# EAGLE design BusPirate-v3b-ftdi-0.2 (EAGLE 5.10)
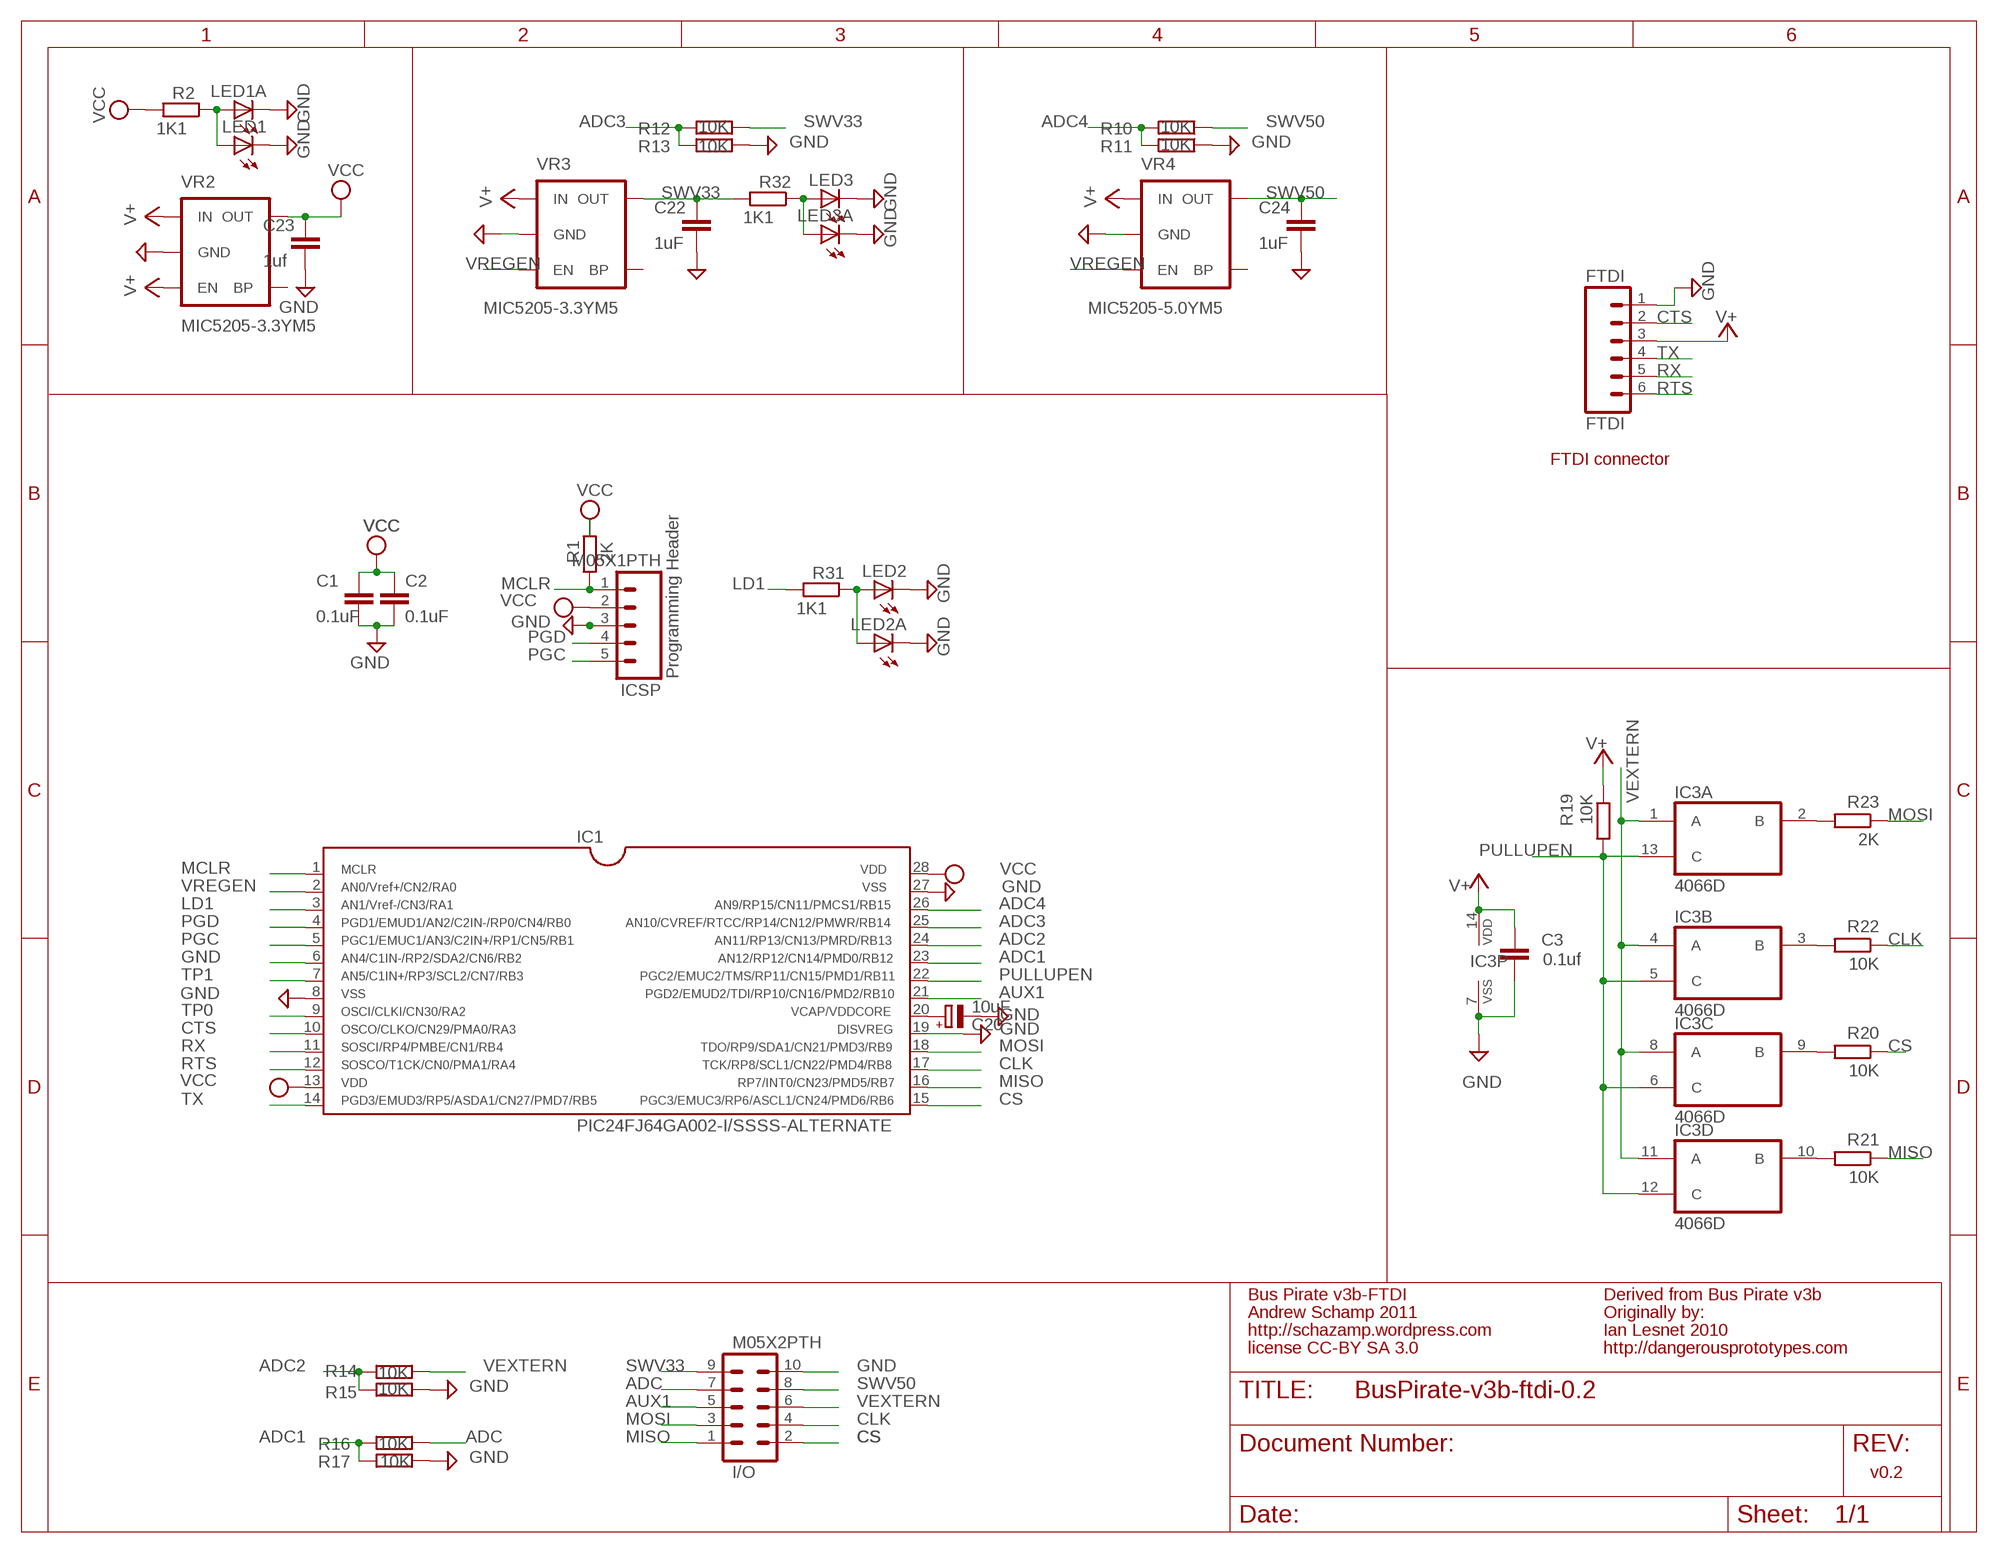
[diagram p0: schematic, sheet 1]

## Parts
C1  0.1uF  C-EUC0805  [C0805]
C2  0.1uF  C-EUC0805  [C0805]
C3  0.1uf  C-EUC0805  [C0805]
C20  10uF  CPOL-EUSMCA  [SMC_A]
C22  1uF  C-EUC0805  [C0805]
C23  1uf  C-EUC0805  [C0805]
C24  1uF  C-EUC0805  [C0805]
FTDI  FTDI  M06LOCK  [1X06_LOCK]
I/O  M05X2PTH  [AVR_ICSP]
IC1  PIC24FJ64GA002-I/SSSS-ALTERNATE  [SSOP28DB]
IC3  4066D  [SO14]
ICSP  M05X1PTH  M05  [1X05]
LED1  LEDCHIP-LED0805  [CHIP-LED0805]
LED1A  LEDCHIP-LED0805  [CHIP-LED0805]
LED2  LEDCHIP-LED0805  [CHIP-LED0805]
LED2A  LEDCHIP-LED0805  [CHIP-LED0805]
LED3  LEDCHIP-LED0805  [CHIP-LED0805]
LED3A  LEDCHIP-LED0805  [CHIP-LED0805]
R1  2K  R-EU_R0805  [R0805]
R2  1K1  R-EU_M0805  [M0805]
R10  10K  R-EU_M0805  [M0805]
R11  10K  R-EU_M0805  [M0805]
R12  10K  R-EU_M0805  [M0805]
R13  10K  R-EU_M0805  [M0805]
R14  10K  R-EU_M0805  [M0805]
R15  10K  R-EU_M0805  [M0805]
R16  10K  R-EU_M0805  [M0805]
R17  10K  R-EU_M0805  [M0805]
R19  10K  R-EU_R0805  [R0805]
R20  10K  R-EU_R0805  [R0805]
R21  10K  R-EU_R0805  [R0805]
R22  10K  R-EU_R0805  [R0805]
R23  2K  R-EU_R0805  [R0805]
R31  1K1  R-EU_M0805  [M0805]
R32  1K1  R-EU_M0805  [M0805]
VR2  MIC5205-3.3YM5  V_REG_LDOSMD  [SOT23-5]
VR3  MIC5205-3.3YM5  V_REG_LDOSMD  [SOT23-5]
VR4  MIC5205-5.0YM5  V_REG_LDOSMD  [SOT23-5]

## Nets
ADC: I/O.7 R16.1
ADC1: IC1.23 R16.2 R17.2
ADC2: IC1.24 R14.2 R15.2
ADC3: IC1.25 R12.2 R13.2
ADC4: IC1.26 R10.2 R11.2
AUX1: I/O.5 IC1.21
CLK: I/O.4 IC1.17 R22.1
CS: I/O.2 IC1.15 R20.1
CTS: FTDI.2 IC1.10
GND: C1.2 C2.2 C3.2 C20.- C22.2 C23.2 C24.2 FTDI.1 I/O.10 IC1.6 IC1.8 IC1.19 IC1.27 IC3.7(P:VSS) ICSP.3 LED1.C LED1A.C LED2.C LED2A.C LED3.C LED3A.C R11.1 R13.1 R15.1 R17.1 VR2.2(GND) VR3.2(GND) VR4.2(GND)
LD1: IC1.3 R31.2
MCLR: IC1.1 ICSP.1 R1.1
MISO: I/O.1 IC1.16 R21.1
MOSI: I/O.3 IC1.18 R23.1
N$1: IC3.2(A:B) R23.2
N$2: IC3.3(B:B) R22.2
N$3: C20.+ IC1.20
N$4: IC3.10(D:B) R21.2
N$5: IC3.9(C:B) R20.2
N$6: LED2.A LED2A.A R31.1
N$7: LED1.A LED1A.A R2.1
N$18: LED3.A LED3A.A R32.1
PGC: IC1.5 ICSP.5
PGD: IC1.4 ICSP.4
PULLUPEN: IC1.22 IC3.5(B:C) IC3.6(C:C) IC3.12(D:C) IC3.13(A:C) R19.2
RTS: FTDI.6 IC1.12
RX: FTDI.5 IC1.11
SWV33: C22.1 I/O.9 R12.1 R32.2 VR3.5(OUT)
SWV50: C24.1 I/O.8 R10.1 VR4.5(OUT)
TP0: IC1.9
TP1: IC1.7
TX: FTDI.4 IC1.14
V+: C3.1 FTDI.3 IC3.14(P:VDD) R19.1 VR2.1(IN) VR2.3(EN) VR3.1(IN) VR4.1(IN)
VCC: C1.1 C2.1 C23.1 IC1.13 IC1.28 ICSP.2 R1.2 R2.2 VR2.5(OUT)
VEXTERN: I/O.6 IC3.1(A:A) IC3.4(B:A) IC3.8(C:A) IC3.11(D:A) R14.1
VREGEN: IC1.2 VR3.3(EN) VR4.3(EN)
Unconnected: VR2.4(BP) VR3.4(BP) VR4.4(BP)

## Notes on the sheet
- FTDI connector
- Programming Header
- Bus Pirate v3b-FTDI | Derived from Bus Pirate v3b
- Andrew Schamp 2011 | Originally by:
- http://schazamp.wordpress.com | Ian Lesnet 2010
- license CC-BY SA 3.0 | http://dangerousprototypes.com
- v0.2

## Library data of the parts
C1-C3 C22-C24 = rcl:C-EU: CAPACITOR, European symbol
C20 = rcl:CPOL-EU: POLARIZED CAPACITOR, European symbol
FTDI = SparkFun:M06: Header 6 Standard 6-pin 0.1" header. Use with straight break away headers (SKU : PRT-00116), right angle break away headers (PRT-00553), swiss pins (PRT-00743), machine pins (PRT-00117), and female headers (PRT-00115). Molex polarized connector foot print use with SKU : PRT-08094 with associated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
I/O = SparkFun:M05X2: Header 5x2 Standard 10-pin dual row 0.1" header. Commonly used with AVR-ISP. Use with Spark Fun Electronics SKU: PRT-00778
IC1 = microchip-pic24:PIC24FJ64GA002-I/SS
IC3 = 40xx:4066: Quad bilateral ANALOG SWITCH
ICSP = SparkFun:M05: Header 5 Standard 5-pin 0.1" header. Use with straight break away headers (SKU : PRT-00116), right angle break away headers (PRT-00553), swiss pins (PRT-00743), machine pins (PRT-00117), and female headers (PRT-00115). Molex polarized connector foot print use with SKU : PRT-08230 with associated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
LED1 LED1A LED2 LED2A LED3 LED3A = led:LED: LED
R1 R2 R19-R23 R31 R32 = rcl:R-EU_: RESISTOR, European symbol
R10-R17 = resistor:R-EU_: RESISTOR, European symbol
VR2-VR4 = SparkFun:V_REG_LDO: Voltage Regulator LDO Standard 150mA LDO voltage regulator in SOT-23 layout. Micrel part MIC5205. BP (by-pass) pin is used to lower output noise with 470pF cap.

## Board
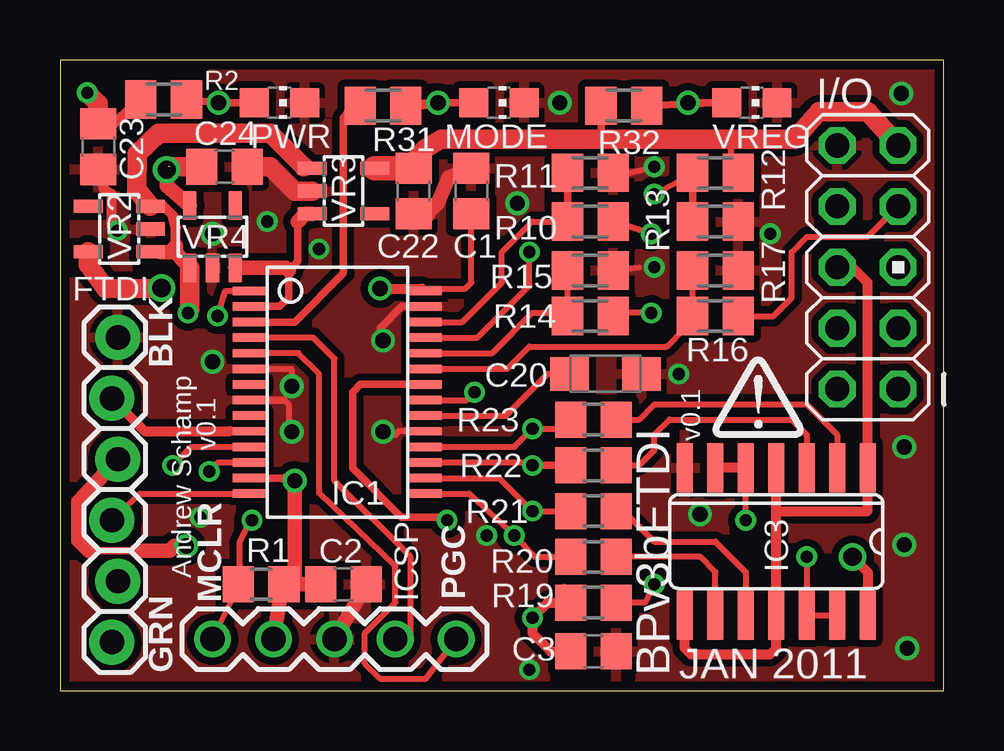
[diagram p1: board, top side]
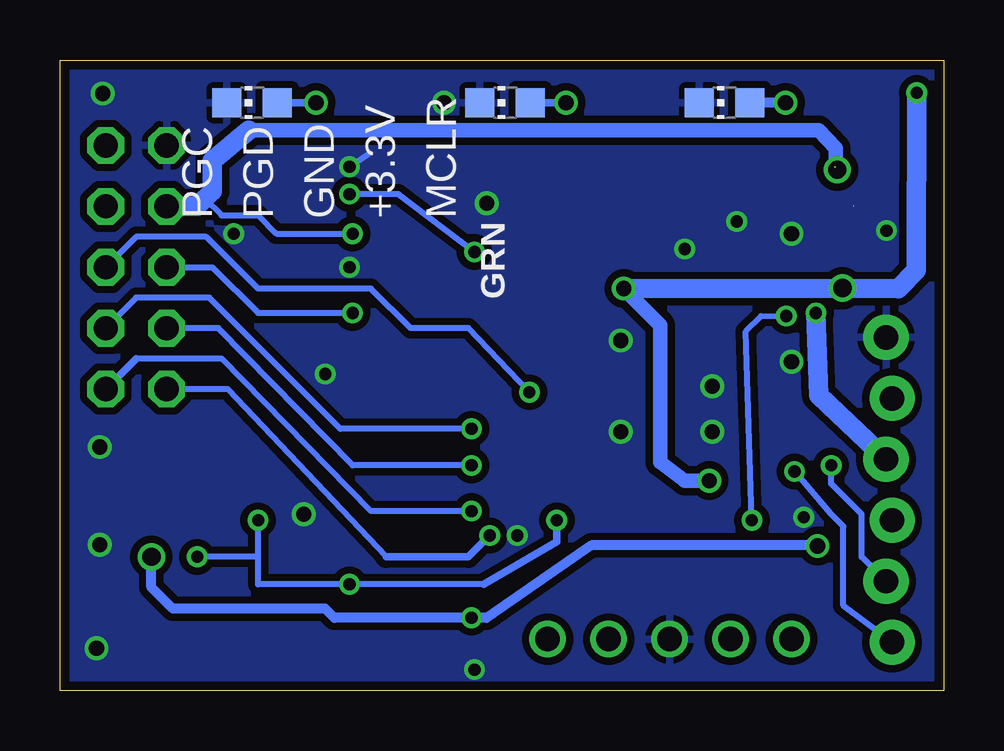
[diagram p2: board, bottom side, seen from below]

Size 36.83 x 26.29 mm. Coordinates in mm from the lower left corner, seen from the top.
Outline: 0,26.29 0,0 36.83,0 36.83,26.29 0,26.29
Copper layers (1*16): Top 0.0356mm / dielectric 1.5011mm / Bottom 0.0356mm
Design rules "LaenPCBOrder-tent": minimum track width 6mil, minimum drill 13mil, track to track 6mil, track to pad 6mil, pad to pad 6mil, via to via 6mil, smd to smd 6mil, copper to edge 15mil, drill to drill 6mil, minimum pad ring 7mil, minimum via ring 7mil, stop-mask expansion 4mil, vias tented up to drill 30mil, thermal gap 10mil

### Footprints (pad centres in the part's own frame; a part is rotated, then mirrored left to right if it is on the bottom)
C0805 = smd 1.3 x 1.5: 1 -0.95,0; 2 0.95,0
SMC_A = smd 1.6 x 1.4: + -1.5,0; - 1.5,0
1X06_LOCK = drill 1.016 pad 1.88 round: 1 0,0; 2 2.54,-0.254; 3 5.08,0; 4 7.62,-0.254; 5 10.16,0; 6 12.7,-0.254
AVR_ICSP = drill 1.016 octagon: 1 -1.27,5.08; 2 1.27,5.08; 3 -1.27,2.54; 4 1.27,2.54; 5 -1.27,0; 6 1.27,0; 7 -1.27,-2.54; 8 1.27,-2.54; 9 -1.27,-5.08; 10 1.27,-5.08
SSOP28DB = smd 0.348 x 1.397: 1 -4.225,-3.656; 2 -3.575,-3.656; 3 -2.925,-3.656; 4 -2.275,-3.656; 5 -1.625,-3.656; 6 -0.975,-3.656; 7 -0.325,-3.656; 8 0.325,-3.656; 9 0.975,-3.656; 10 1.625,-3.656; 11 2.275,-3.656; 12 2.925,-3.656; 13 3.575,-3.656; 14 4.225,-3.656; 15 4.225,3.656; 16 3.575,3.656; 17 2.925,3.656; 18 2.275,3.656; 19 1.625,3.656; 20 0.975,3.656; 21 0.325,3.656; 22 -0.325,3.656; 23 -0.975,3.656; 24 -1.625,3.656; 25 -2.275,3.656; 26 -2.925,3.656; 27 -3.575,3.656; 28 -4.225,3.656
SO14 = smd 0.66 x 2.032: 1 -3.81,-3.073; 2 -2.54,-3.073; 3 -1.27,-3.073; 4 0,-3.073; 5 1.27,-3.073; 6 2.54,-3.073; 7 3.81,-3.073; 8 3.81,3.073; 9 2.54,3.073; 10 1.27,3.073; 11 0,3.073; 12 -1.27,3.073; 13 -2.54,3.073; 14 -3.81,3.073
1X05 = drill 1.016 round: 1 0,0; 2 2.54,0; 3 5.08,0; 4 7.62,0; 5 10.16,0
CHIP-LED0805 = smd 1.2 x 1.2: A 0,-1.05; C 0,1.05
R0805 = smd 1.3 x 1.5: 1 -0.95,0; 2 0.95,0
M0805 = smd 1.3 x 1.6: 1 -0.95,0; 2 0.95,0
SOT23-5 = smd 0.55 x 1.2: 1 -0.95,-1.3; 2 0,-1.3; 3 0.95,-1.3; 4 0.95,1.3; 5 -0.95,1.3

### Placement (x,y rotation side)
C1  17.14,20.83 90 top
C2  11.81,4.45 0 top
C3  22.23,1.65 0 top
C20  22.73,13.21 0 top
C22  14.73,20.83 270 top
C23  1.6,22.68 270 top
C24  6.86,21.84 0 top
FTDI  2.41,14.73 270 top
I/O  33.66,17.65 180 top
IC1  11.56,12.45 270 top
IC3  29.84,6.22 180 top
ICSP  6.35,2.16 0 top
LED1  9.14,24.51 270 top
LED1A  9.14,24.51 90 bottom
LED2  18.29,24.51 270 top
LED2A  18.29,24.51 90 bottom
LED3  28.83,24.51 270 top
LED3A  28.83,24.51 90 bottom
R1  8.38,4.45 0 top
R2  4.32,24.64 180 top
R10  22.1,19.56 180 top
R11  22.1,21.59 180 top
R12  27.3,21.59 180 top
R13  27.3,19.56 180 top
R14  22.1,15.62 180 top
R15  22.1,17.53 180 top
R16  27.3,15.62 180 top
R17  27.3,17.53 180 top
R19  22.23,3.68 0 top
R20  22.23,5.59 0 top
R21  22.23,7.49 0 top
R22  22.23,9.4 0 top
R23  22.23,11.3 0 top
R31  13.46,24.38 180 top
R32  23.5,24.38 180 top
U$1  [DP-LOGO]  27.18,10.54 0 top
VR2  2.47,19.25 90 top
VR3  11.81,20.83 270 top
VR4  6.35,18.92 0 top

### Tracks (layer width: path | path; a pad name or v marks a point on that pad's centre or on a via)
ADC
  Top 0.254: I/O.7 33.66,18.92 31.11,18.92 30.48,18.29 30.48,16.38 29.72,15.62 R16.1
ADC1
  Top 0.254: R17.2 R16.2 26.36,15.11 26.04,15.11 25.27,14.35 19.56,14.35 18.63,13.42 IC1.23
ADC2
  Top 0.254: R15.2 R14.2 21.15,15.75 19.68,15.75 18.01,14.07 IC1.24
ADC3  (via drill 0.51)
  Top 0.254: v19.56,18.29 19.56,16.89 17.39,14.72 IC1.25 | v24.77,20.7 26.23,21.46 R12.2
  Top 0.305: R13.2 R12.2 26.36,21.78
  Bottom 0.254: v24.77,20.7 22.73,20.7 v19.56,18.29
ADC4
  Top 0.254: IC1.26 16.77,15.37 18.41,17.02 18.41,18.29 19.68,19.56 R10.2
  Top 0.305: R10.2 R11.2
  Top 0.406: R10.2 20.95,19.56
AUX1  (via drill 0.51)
  Top 0.254: IC1.21 16.95,12.12 v17.27,12.45
  Bottom 0.254: I/O.5 33.66,18.92 30.73,18.92 28.57,16.76 23.88,16.76 22.23,15.11 19.81,15.11 v17.27,12.45
CLK  (via drill 0.51)
  Top 0.254: IC1.17 19.56,9.52 v19.68,9.4
  Top 0.305: v19.68,9.4 R22.1
  Bottom 0.254: I/O.4 30.23,15.11 24.64,9.4 v19.68,9.4
CS  (via drill 0.51)
  Top 0.254: R20.1 19.81,5.59 v18.92,6.48 17.14,8.13 17.05,8.22 IC1.15
  Bottom 0.254: I/O.2 29.84,12.57 23.24,5.59
  Bottom 0.305: v18.92,6.48 19.81,5.59 23.24,5.59
CTS
  Top 0.254: 7.09,10.82 IC1.10
  Top 0.406: 7.09,10.82 3.53,10.82 FTDI.2
GND  (via drill 0.51, 0.64)
  Top 0.254: R15.1 24.13,17.65 | 9.34,12.12 9.53,11.94 9.53,10.92 v9.65,10.79 | IC1.19 14.12,10.82 13.97,10.67 | IC1.6 9.65,13.42 v9.65,12.7 | R11.1 23.75,21.59 v24.77,21.84
  Top 0.305: IC1.27 14.24,16.02 13.34,15.11 13.34,14.73 v13.46,14.61 | IC1.8 9.34,12.12
  Top 0.406: C23.2 1.86,20.88 2.16,20.7 2.16,19.33 v2.39,19.18
  Top 0.61: 15.24,19.88 15.75,20.32 16.19,21.4 C1.2 | ICSP.3 12.45,3.88 C2.2
  Top 0.813: VR3.2 9.78,20.83 8.76,21.84 C24.2 | C22.2 15.24,19.88
  Bottom 0.254: v24.77,21.84 24,22.35
  other vias: 26.67,7.37 35.18,6.1 35.31,1.78 25.78,13.21 24.77,17.65 19.05,20.32 20.83,24.51 13.46,10.79 35.18,10.16 35.05,24.89 6.35,19.05 6.35,13.72 8.64,19.56 29.59,19.05 5.84,7.24 17.78,6.48 19.56,0.89 10.79,18.41
  pour Top (isolate 0.305): -0.25,26.8 36.7,26.8 36.7,0.13 -0.25,0.13
  pour Bottom (isolate 0.305): 0,26.54 36.7,26.54 36.83,0.13 0.13,0.13
LD1
  Top 0.254: 11.81,23.88 12.06,24.32 R31.2
  Top 0.305: IC1.3 9.78,15.37 11.81,17.4 11.81,23.88
MCLR  (via drill 0.51)
  Top 0.254: IC1.1 6.89,16.67 v6.57,15.63 | v8,7.11 7.75,6.73 7.49,6.22 7.49,5.27 R1.1 7.37,4.19 ICSP.1
  Bottom 0.254: v6.57,15.63 7.62,15.62 8.26,14.99 v8,7.11
MISO  (via drill 0.51)
  Top 0.254: v19.68,7.49 R21.1 | v19.68,7.49 19.58,7.6 | IC1.16 18.31,8.87 v19.68,7.49
  Bottom 0.254: 33.66,13.84 30.1,13.84 23.88,7.49 v19.68,7.49
  Bottom 0.305: 33.66,13.84 I/O.1
MOSI  (via drill 0.51)
  Top 0.254: IC1.18 18.93,10.17 v19.68,10.92 20.89,10.92 R23.1
  Bottom 0.254: I/O.3 33.66,16.38 30.61,16.38 25.15,10.92 v19.68,10.92
N$1
  Top 0.254: IC3.2 32.38,10.67 31.11,11.94 24.77,11.94 24.13,11.3 R23.2
N$2
  Top 0.254: R22.2 24.13,9.4 24.77,10.03 24.77,10.67 25.4,11.3 30.48,11.3 31.11,10.67 IC3.3
N$3
  Top 0.254: IC1.20 18.58,11.47 20.32,13.21 C20.+
N$4
  Top 0.254: R21.2 23.5,7.49 24.77,6.22 27.3,6.22 28.57,4.95 IC3.10
N$5
  Top 0.254: R20.2 26.67,5.59 27.3,4.95 IC3.9
N$6  (via drill 0.64)
  Top 0.305: 15.59,24.48 LED2A.A v15.75,24.51
  Top 0.406: R31.1 15.59,24.48
  Bottom 0.305: v15.75,24.51 LED2A.A
N$7  (via drill 0.64)
  Top 0.305: LED1A.A v6.6,24.51 R2.1
  Bottom 0.406: v6.6,24.51 LED1A.A
N$18  (via drill 0.64)
  Top 0.305: R32.1 27.75,24.54 | LED3A.A v26.16,24.51
  Top 0.406: 27.75,24.54 LED3A.A
  Bottom 0.305: v26.16,24.51 LED3A.A
PGC
  Top 0.254: IC1.5 9.93,14.07 10.79,13.21 10.79,8.26 13.97,5.21 13.97,3.68 12.7,2.41 12.7,1.14 13.34,0.51 15.24,0.51 ICSP.5
PGD
  Top 0.254: IC1.4 10.55,14.72 11.43,13.84 11.43,8.76 14.61,5.59 14.61,2.41 ICSP.4
PULLUPEN  (via drill 0.51)
  Top 0.254: v31.11,5.59 IC3.12 IC3.13 | v28.57,7.11 IC3.5 | R19.2 24.38,3.68 v24.77,4.45
  Top 0.305: IC1.22 12.52,12.77 12.19,12.45 12.19,9.27 14.22,7.24 16,7.24 v16.13,7.11
  Top 0.406: IC3.5 IC3.6
  Bottom 0.254: 28.57,5.59 28.57,4.45 v24.77,4.45 19.18,4.45 | 28.57,5.59 v28.57,7.11 | 28.57,5.59 v31.11,5.59
  Bottom 0.305: v16.13,7.11 16.13,6.22 19.18,4.45
RTS  (via drill 0.51)
  Top 0.254: IC1.12 6.6,9.52 v6.22,9.14
  Bottom 0.254: v6.22,9.14 4.7,7.37 4.19,6.86 4.19,3.56 FTDI.6
RX  (via drill 0.51)
  Top 0.254: IC1.11 5.47,10.17 v4.7,9.4
  Bottom 0.254: FTDI.5 3.43,5.59 3.43,7.37 4.7,8.64 v4.7,9.4
SWV33
  Top 0.254: R12.1 27.94,21.46 27.94,22.99
  Top 0.305: 22.55,22.8 R32.2
  Top 0.406: R32.2 22.67,24.51 | 24.64,22.99 22.55,22.8
  Top 0.61: 14.48,21.78 C22.1 13.93,21.78
  Top 0.813: I/O.9 33.66,24.13 31.62,24.13 30.61,22.99 27.94,22.99 24.64,22.99 15.88,22.99 15.24,22.61 14.48,21.78
  Top 1.016: 13.93,21.78 VR3.5
SWV50  (via drill 0.51, 0.76)  (1 unrouted)
  Top 0.254: v24.64,19.05 R10.1
  Top 0.61: 4.45,21.65 4.45,21.05 VR4.5
  Top 0.762: 4.45,21.65 v4.45,21.72
  Top 0.813: C24.1 4.57,21.84 v4.45,21.72
  Bottom 0.254: v24.64,19.05 27.81,19.05 28.57,19.81 30.1,19.81 30.8,20.51
  Bottom 0.61: 28.96,23.37 5.21,23.37 4.51,22.61 4.51,21.84
  Bottom 0.813: I/O.8 31.11,20.19 30.8,20.51 30.48,20.83 30.48,22.1 28.96,23.37
TX
  Top 0.254: IC1.14 3.34,8.22 FTDI.4
V+  (via drill 0.51, 0.64, 0.76)  (1 unrouted)
  Top 0.254: IC3.14 33.66,2.73 | 21.02,4.25 R19.1 21.27,3.36
  Top 0.305: 1.19,5.84 3.17,5.84
  Top 0.406: 21.02,4.25 21.02,3.75 20.95,3.68 20.32,3.68 v19.68,3.05 19.68,2.41 20.45,1.65 C3.1 | IC3.14 33.66,4.95 v33.02,5.59 | 10.16,21.84 10.45,21.84 VR3.1 | 3.75,20.19 4.32,20.19 4.7,19.81 4.83,19.3 4.83,18.54 4.83,18.48 | 4.19,18.29 3.53,18.29 VR2.1
  Top 0.61: FTDI.3 0.76,7.87 0.76,6.27 1.19,5.84 | v5.26,6.04 4.77,6.04 4.57,5.84 3.17,5.84 | 4.19,18.29 4.57,18.29 4.83,18.54 | 4.83,18.48 4.85,18.23 VR4.1 | v5.33,15.75 5.41,15.9
  Top 0.813: 10.16,21.84 8.76,23.24 4.11,23.24 3.21,22.38 3.19,20.83 3.32,20.75 3.75,20.19 | 5.41,15.9 VR4.1
  Bottom 0.406: v33.02,5.59 33.02,4.32 32.13,3.43 25.78,3.43 25.4,3.05 v19.68,3.05 19.05,3.05 14.69,6.07 5.29,6.07 v5.26,6.04
  Bottom 0.813: v5.33,15.75 5.21,12.32 FTDI.3
VCC  (via drill 0.51, 0.64, 0.76)
  Top 0.254: R1.2 9.53,4.51 | 15.09,16.76 16.89,16.76 17.14,17.02 C1.1
  Top 0.305: IC1.13 9.67,8.87 v9.78,8.76 | 15.09,16.76 15.12,16.76 IC1.28
  Top 0.406: 10.29,4.51 C2.1 9.78,4.38 | v9.78,8.76 9.42,8.87 | v13.34,16.76 15.09,16.76 | C23.1 1.98,23.37 R2.2
  Top 0.61: C2.1 R1.2 9.27,4.45 ICSP.2 | 9.78,4.38 v9.78,8.76
  Top 0.813: VR2.5 1.17,17.75 1.91,16.76 v4.23,16.78 | C23.1 1.6,24.46 v1.13,24.93
  Bottom 0.61: v9.78,8.76 10.79,8.76 11.81,9.53 11.81,15.24 v13.34,16.76
  Bottom 0.813: v13.34,16.76 v4.23,16.78 1.91,16.76 1.14,17.53 v1.13,24.93
VEXTERN  (via drill 0.51)
  Top 0.254: v24.64,15.75 23.18,15.75 R14.1
  Top 0.406: 29.84,7.49 33.66,7.49 IC3.1 33.66,17.02 33.02,17.65 I/O.6 | IC3.8 26.04,1.78 26.29,1.52 29.59,1.52 29.84,1.78 IC3.11 29.84,7.49 | 29.84,7.49 IC3.4
  Bottom 0.254: I/O.6 30.48,17.65 28.57,15.75 v24.64,15.75
VREGEN
  Top 0.305: IC1.2 9.16,16.02 9.53,16.38 9.53,17.53 9.91,17.91 9.91,19.56
  Top 0.61: VR4.3 9.43,17.62 9.53,17.53 | VR3.3 10.23,19.88 9.91,19.56

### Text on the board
tNames: PWR | MODE | VREG | BLK | v0.1 | v0.1 | Andrew Schamp | MCLR | PGC | GRN | BPv3bFTDI | JAN 2011
bNames: GRN | MCLR | +3.3V | GND | PGD | PGC
Reference: MCLR | +3.3V | GND | DATA | CLOCK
